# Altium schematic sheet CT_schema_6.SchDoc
size 399 x 245 mm
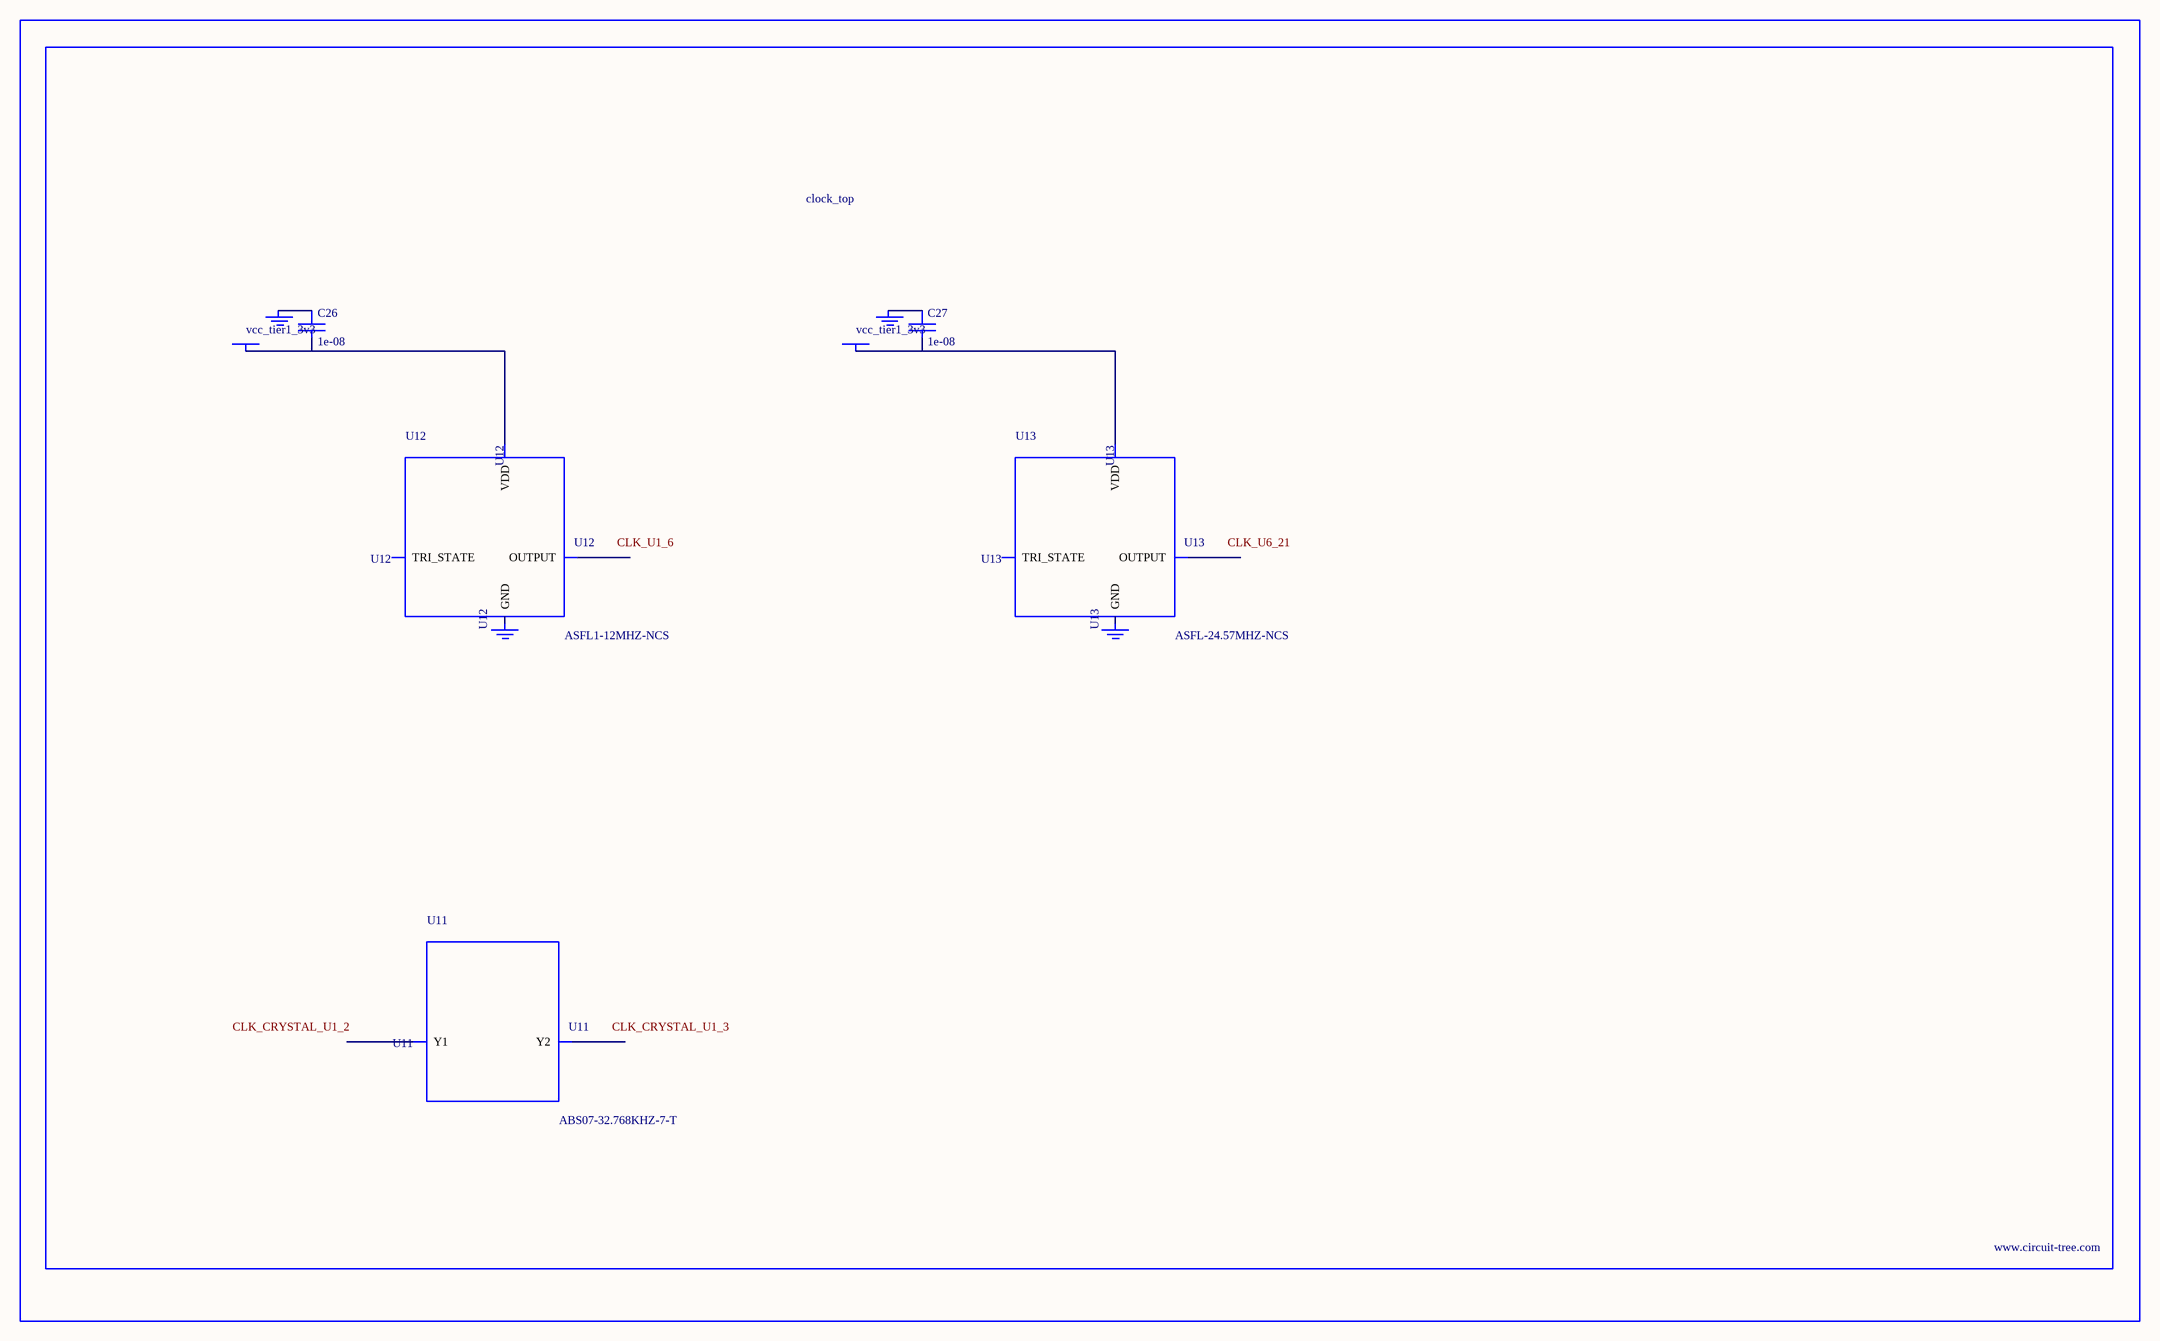
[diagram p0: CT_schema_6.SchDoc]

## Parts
BORDER5  (no value)
C26  1e-08  [C0402]
C27  1e-08  [C0402]
GND_INSTANCE_5_0  (no value)
GND_INSTANCE_5_1  (no value)
GND_INSTANCE_5_2  (no value)
GND_INSTANCE_5_3  (no value)
POWER_INSTANCE_5_0  vcc_tier1_3v3
POWER_INSTANCE_5_1  vcc_tier1_3v3
U11  ABS07-32.768KHZ-7-T  [ABS07-32.768KHZ-7-T]
U12  ASFL1-12MHZ-NCS  [ASFL1]
U13  ASFL-24.57MHZ-NCS  [ASFL1]

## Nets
NetC26_1: C26.1 GND_INSTANCE_5_0.0(GND)
NetC26_2: C26.2 POWER_INSTANCE_5_0.0(PWR) U12.4(VDD)
NetC27_1: C27.1 GND_INSTANCE_5_2.0(GND)
NetC27_2: C27.2 POWER_INSTANCE_5_1.0(PWR) U13.4(VDD)

Not connected (* = marked no-connect by the designer): GND_INSTANCE_5_1 0(GND); GND_INSTANCE_5_3 0(GND); U11 1(Y1) 2(Y2); U12 1(TRI_STATE) 2(GND) 3(OUTPUT); U13 1(TRI_STATE) 2(GND) 3(OUTPUT)

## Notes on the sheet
- Labels drawn without touching a wire or pin: CLK_CRYSTAL_U1_2, CLK_CRYSTAL_U1_3, CLK_U1_6, CLK_U6_21

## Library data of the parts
BORDER5 = BORDER_PAGE5
C26 C27 = C0402C103K3RAC
GND_INSTANCE_5_0-GND_INSTANCE_5_3 = GND
POWER_INSTANCE_5_0 POWER_INSTANCE_5_1 = PWR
